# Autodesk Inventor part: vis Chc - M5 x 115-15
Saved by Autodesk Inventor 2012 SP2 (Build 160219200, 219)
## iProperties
Created: 2013-04
Part Number: vis Chc - M5 x 115-15
Material: Default
Document SubType Name: Modeling
Designer: papa
Density: 1 g/cm^3
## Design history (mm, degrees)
node "vis Chc - M5 x 115-151"
node "vis Chc - M5 x 115-15"
node "Base1"
